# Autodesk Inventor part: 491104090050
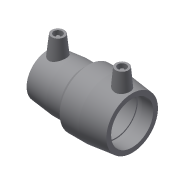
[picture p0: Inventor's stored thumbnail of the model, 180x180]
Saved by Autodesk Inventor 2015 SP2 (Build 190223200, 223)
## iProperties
Created: 2017-06
Part Number: 491104090050
Material: Generic
Description: PLASSON REDUCING COUPLER 90-50
Document SubType Name: Modeling
Designer: KIM
Mass: 54.8237 g
Surface Area: 155.252 cm^2
Volume: 54.8237 cm^3
Density: 1 g/cm^3
Appearance: Default
Author: KIM
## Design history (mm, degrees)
derived "491104.ipt"
feature "Solid1::491104.ipt"
tag "TaggingFeature1"
body "Solid1"
other parameters: "d0" = 143, "d2" = 69, "d3" = 49, "d4" = 29.4, "d5" = 62.1, "d8" = 168 deg, "d10" = 19.6, "d11" = 6.53333, "d13" = 143, "d14" = 17.6296, "d15" = 49, "d19" = 2.45, "d20" = 168 deg, "d22" = 108.92847, "d25" = 135 deg, "d29" = 53, "d30" = 15, "d31" = 54.34, "d34" = 6 deg, "d35" = 15, "d38" = 25.5, "d39" = 5 deg, "d41" = 4, "d42" = 14, "d43" = 0, "d45" = 4, "d46" = 14, "d47" = 0, "d48" = 69, "d50" = 116, "d52" = 45, "d53" = 28.4, "d54" = 9.46667, "d55" = 168 deg, "d56" = 42.6, "d57" = 71, "d58" = 104.4, "d59" = 2.45, "d60" = 135 deg, "d61" = 78, "d62" = 15, "d64" = 4, "d66" = 5 deg, "d67" = 14, "d68" = 0, "d69" = 54.34, "d70" = 69, "d71" = 116, "d73" = 109.04, "d76" = 2.45, "d77" = 168 deg, "d79" = 2.45, "d80" = 71, "d81" = 45, "d82" = 64.86, "d83" = 120 deg, "d88" = 15, "d89" = 28.5, "d90" = 5 deg, "d92" = 4, "d93" = 14, "d94" = 0, "d95" = 3, "d96" = 0, "d97" = 3, "d98" = 0, "d99" = 14.21, "d100" = 3.5525, "d101" = 62.9142, "d102" = 20 deg, "d103" = 20.59, "d104" = 5.1475, "d105" = 105.7688, "d106" = 3.60705, "d107" = 3, "d108" = 0, "d109" = 3, "d110" = 0, "L_" = 143, "L_2" = 49, "D_1" = 69, "A_1" = 53, "d_2" = 12, "L_1" = 71, "A_" = 78, "D_" = 116
